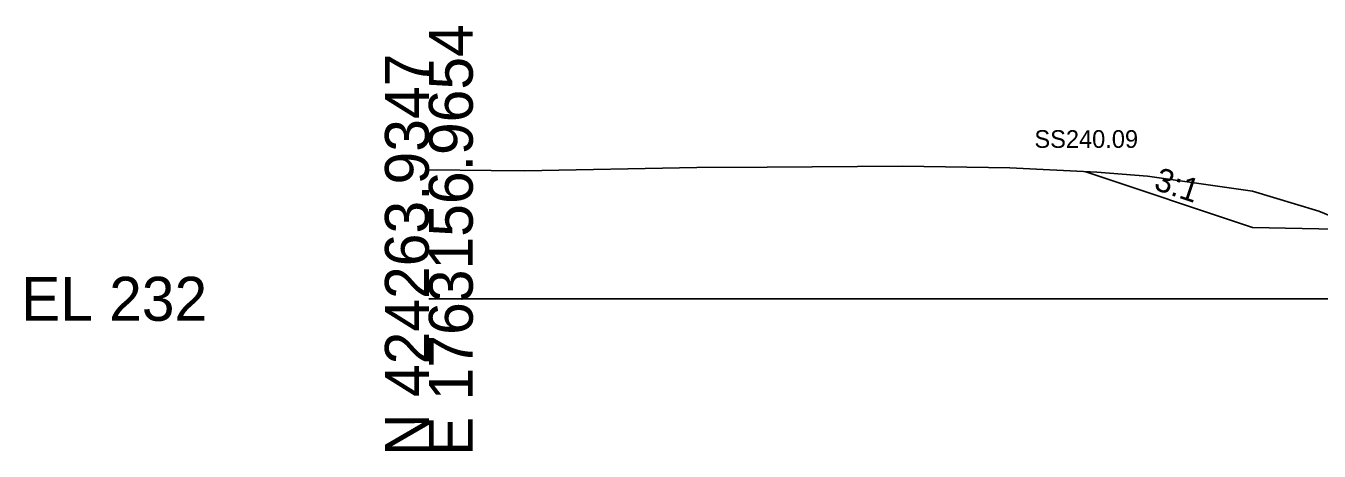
# Model space of a CAD drawing. Extents: x -26 to 3203, y -11010 to 4024.
# Drawn here: x 1974.3 to 2056.8, y -4509.7 to -4482.6 of the extents above; entities that cross this region are included whole.
import ezdxf

# ---------------------------------------------------------------- set-up
doc = ezdxf.new("R2010")
doc.units = 0
for name, color, linetype in [('Default', 7, 'Continuous'), ('Exist Cross Section Cell', 7, 'Continuous'), ('Exist XS Ground Line', 7, 'Continuous'), ('Prop CMT Slope Grass', 7, 'Continuous'), ('Prop XS Side Slope Text', 7, 'Continuous'), ('Prop XS SS Elevation Text', 7, 'Continuous'), ('Scratch_Level_0', 7, 'Continuous')]:
    doc.layers.add(name, color=color, linetype=linetype)

msp = doc.modelspace()

# ---------------------------------------------------------------- linework, layer by layer
at = {"layer": 'Exist Cross Section Cell'}
msp.add_line((2000, -4500), (2100, -4500), dxfattribs=at)
at = {"layer": 'Exist XS Ground Line'}
msp.add_lwpolyline([(2000, -4491.797), (2003.977, -4491.839), (2006.087, -4491.857), (2017.083, -4491.646), (2021.558, -4491.625), (2030.189, -4491.559), (2037.028, -4491.667), (2042.583, -4491.946), (2045.805, -4492.19), (2045.819, -4492.188), (2052.499, -4493.138), (2056.737, -4494.417), (2058.445, -4495.114)], dxfattribs=at)
msp.add_lwpolyline([(2000, -4491.797), (2003.977, -4491.839), (2006.087, -4491.857), (2017.083, -4491.646), (2021.558, -4491.625), (2030.189, -4491.559), (2037.028, -4491.667), (2042.583, -4491.946), (2045.805, -4492.19), (2045.819, -4492.188), (2052.499, -4493.138), (2056.737, -4494.417), (2058.445, -4495.114)], dxfattribs=at)
msp.add_lwpolyline([(2000, -4491.797), (2003.977, -4491.839), (2006.087, -4491.857), (2017.083, -4491.646), (2021.558, -4491.625), (2030.189, -4491.559), (2037.028, -4491.667), (2042.583, -4491.946), (2045.805, -4492.19), (2045.819, -4492.188), (2052.499, -4493.138), (2056.737, -4494.417), (2058.445, -4495.114)], dxfattribs=at)
msp.add_lwpolyline([(2000, -4491.797), (2003.977, -4491.839), (2006.087, -4491.857), (2017.083, -4491.646), (2021.558, -4491.625), (2030.189, -4491.559), (2037.028, -4491.667), (2042.583, -4491.946), (2045.805, -4492.19), (2045.819, -4492.188), (2052.499, -4493.138), (2056.737, -4494.417), (2058.445, -4495.114)], dxfattribs=at)
msp.add_lwpolyline([(2000, -4491.797), (2003.977, -4491.839), (2006.087, -4491.857), (2017.083, -4491.646), (2021.558, -4491.625), (2030.189, -4491.559), (2037.028, -4491.667), (2042.583, -4491.946), (2045.805, -4492.19), (2045.819, -4492.188), (2052.499, -4493.138), (2056.737, -4494.417), (2058.445, -4495.114)], dxfattribs=at)
at = {"layer": 'Prop CMT Slope Grass'}
msp.add_lwpolyline([(2061.999, -4495.642), (2052.499, -4495.452), (2041.874, -4491.91)], dxfattribs=at)

# ---------------------------------------------------------------- texts
at = {"layer": 'Default'}
msp.add_text('-', height=0.0001, dxfattribs=at).set_placement((2000, -4500))
at = {"layer": 'Exist Cross Section Cell'}
for s, p in [('E 1763156.9654', (2002.8, -4510)), ('N 424263.9347', (2000, -4510))]:
    msp.add_text(s, height=2.8, rotation=90, dxfattribs=at).set_placement(p)
msp.add_text('EL 232', height=2.8, dxfattribs=at).set_placement((1974, -4501.4))
at = {"layer": 'Prop XS Side Slope Text'}
msp.add_text('3:1', height=1.5, rotation=341.56507, dxfattribs=at).set_placement((2046.153, -4493.02))
at = {"layer": 'Prop XS SS Elevation Text'}
msp.add_text('SS240.09', height=1.125, dxfattribs=at).set_placement((2038.606, -4490.388))
at = {"layer": 'Scratch_Level_0'}
for s, p in [('Exterior Boundary', (2041.715, -4491.92)), ('LT_Slope_Cut', (2041.77, -4491.92)), ('LT_CSLP_Pnt', (2052.401, -4495.462))]:
    msp.add_text(s, height=0.02, dxfattribs=at).set_placement(p)

doc.saveas('drawing.dxf')
